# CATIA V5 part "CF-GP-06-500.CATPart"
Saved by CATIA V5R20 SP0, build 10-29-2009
Part number: CF-GP-06-500
Definition: NONE
Nomenclature: CF-GP-06-500
Source: Unknown
Description: CF-GP-06-500
Bounding box of the stored display mesh (mm): x 0 to 500, y 0 to 6, z -8.5 to 8.5
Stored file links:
  C:\Users\Utente\Desktop\IO LAVORO\3D X SITO CF\X SITO\PLASTICA\CF-GP\CF-GP-06-500.CATPart
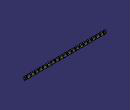
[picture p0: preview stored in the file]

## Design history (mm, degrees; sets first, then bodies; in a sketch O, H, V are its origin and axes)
Body1 "CF-GP-06-500" (main body)
  Solid1: solid without history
